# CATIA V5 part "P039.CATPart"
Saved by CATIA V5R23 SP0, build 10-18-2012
Part number: P039
Definition: Vis Chc M6x50
Description: Vis Chc M6x50
Publications: "Mating Edge", "Axis"
Bounding box of the stored display mesh (mm): x -50 to 6, y -5 to 5, z -5 to 5
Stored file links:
  C:\wamp\www\COURS\CONCEPTION GMP1\TITRE 02-SEMESTRE 2\03-TP7-PRESSE MECANIQUE\eleve\P039.CATPart
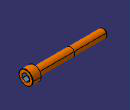
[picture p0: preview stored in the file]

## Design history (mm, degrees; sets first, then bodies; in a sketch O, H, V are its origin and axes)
Parameters
  Material = "St"
  d_dia = 6 mm
  l_nom = 50 mm
  k_head_depth_max = 6 mm
  s_nom = 5 mm
  r_min = 0.25 mm
  ds_max = 6 mm
  e = 5.72 mm
  t_min = 3 mm
  p_pitch = 1 mm
  Threading = 24 mm
  dk_max = 10 mm
  PartNumber = "ISO 4762 Vis Chc M6x50"
Body1 "PartBody" (main body)
  Sketch1 on yz-plane, origin (0, 0, 0), H (0, 1, 0), V (0, 0, 1)
    circle A1 centre (0, 0) radius 5
    radius A1 = 5 {= dk_max /2}
  Pad1: profile Sketch1, direction (1, 0, 0), length 6 {= k_head_depth_max}
  Fillet1: radius 0.25 {= r_min}, on edge [face of Pad1 | face of Pad1]
  Body2
    Sketch2 on face of Pad1, origin (6, 0, 0), H (0, 1, 0), V (0, 0, 1)
      point P1 (2.5, -1.4434)
      point P2 (2.5, 1.4434)
      point P3 (0, 2.8868)
      point P4 (-2.5, 1.4434)
      point P5 (-2.5, -1.4434)
      point P6 (0, -2.8868)
      point P7 (2.5, 0)
      line L1 (2.5, -1.4434) -> (2.5, 1.4434)
      line L2 (2.5, 1.4434) -> (0, 2.8868)
      line L3 (0, 2.8868) -> (-2.5, 1.4434)
      line L4 (-2.5, 1.4434) -> (-2.5, -1.4434)
      line L5 (-2.5, -1.4434) -> (0, -2.8868)
      line L6 (0, -2.8868) -> (2.5, -1.4434)
      construction line L7 (0, 0) -> (2.5, 0)
      construction circle A1 centre (0, 0) radius 2.8868
      construction arc A2 centre (-2.5, -1.4434) radius 2.8868 from (-2.5, 1.4434) to (0, -2.8868) cw
      construction arc A3 centre (2.5, 1.4434) radius 2.8868 from (0, 2.8868) to (2.5, -1.4434) ccw
      point P8 (-2.5, -1.4434)
      point P9 (2.5, 1.4434)
      distance L1 L4 = 5 {= s_nom}
      horizontal: L7 H
      coincidence: A1 P1, A1 P2, A1 P3, A1 P4, A1 P5, A1 P6, A2 P4, A2 P6, A2 O, P8 P5, A3 P3, A3 P1, A3 O, P9 P2
      midpoint: P7 L1
    Pad2: profile Sketch2, direction (-1, 0, 0), length 4.6484 {= t_min +(e /3.47)}
    Body3
      Sketch3 on zx-plane, origin (0, 0, 0), H (-1, 0, 0), V (0, 0, 1)
        point P1 (-1.3488, 0)
        line L1 (-1.3488, 0) -> (-3, 2.86)
        line L2 (-3, 2.86) -> (-6, 2.86)
        line L3 (-6, 2.86) -> (-6, 0)
        axis line L4 (-46.2384, 0) -> (26.3409, 0)
        reference projected line E1 (-6, -6.9227) -> (-6, 6.9227) from edge [face of Pad2 | face of Pad2]
        length L2 = 3 {= t_min}
        angle L1 L4 = 60
        distance L2 L4 = 2.86 {= e /2}
        horizontal: L2 H, L4 H
        perpendicularity: L3 L2
        fix: L4
        coincidence: L3 E1, P1 L4
      Shaft1: profile Sketch3, axis Sketch3.L4, angle 360
    Intersect1: tool Body3
  Remove1: tool Body2
  Sketch4 on xy-plane, origin (0, 0, 0), H (1, 0, 0), V (0, 1, 0)
    line L1 (0, 0) -> (0, 3)
    line L2 (0, 3) -> (-26, 3)
    line L3 (-26, 3) -> (-26, 2.9268)
    line L4 (-26, 2.9268) -> (-50, 2.9268)
    line L5 (-50, 2.9268) -> (-50, 0)
    axis line L6 (-192.3446, 0) -> (99.1594, 0)
    distance L5 L1 = 50 {= l_nom}
    distance L3 L5 = 24 {= Threading}
    distance L2 L6 = 3 {= ds_max /2}
    distance L4 L6 = 2.9268 {= d_dia /2.05}
    vertical: L1 V, L3 V, L5 V
    horizontal: L2 H, L4 H, L6 H
    fix: L6
  Shaft2: profile Sketch4, axis Sketch4.L6, angle 360
  Fillet2: radius 0.25 {= r_min}, on edge [face of Shaft2 | face of Pad1]
  Chamfer1: length 1 {= p_pitch}, angle 45, on edge [face of Shaft2 | face of Shaft2]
